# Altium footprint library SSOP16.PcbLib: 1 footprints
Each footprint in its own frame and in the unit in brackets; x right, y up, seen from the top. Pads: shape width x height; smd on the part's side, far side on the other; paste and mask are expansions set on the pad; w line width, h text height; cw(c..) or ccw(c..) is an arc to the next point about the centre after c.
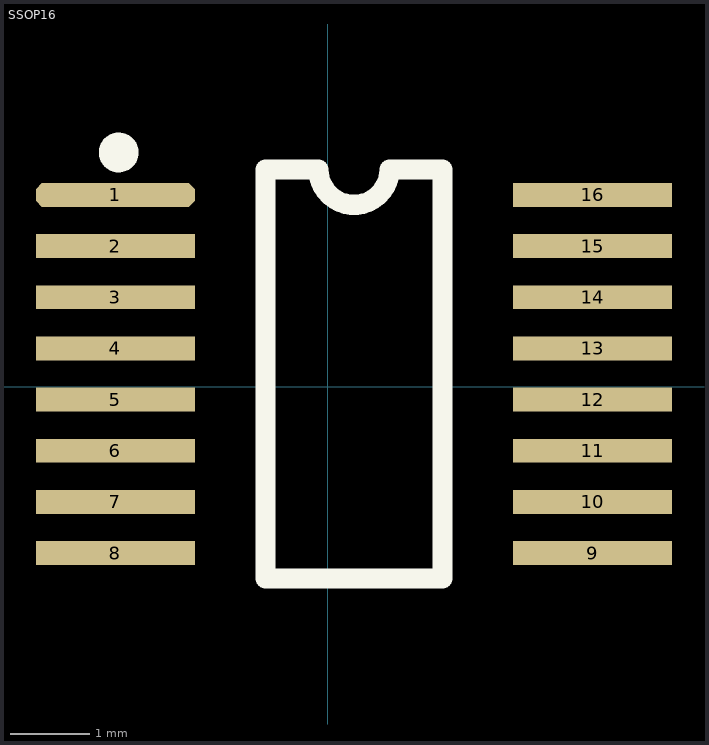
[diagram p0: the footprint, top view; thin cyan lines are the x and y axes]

## SSOP16 [mm] "SOP, 16-Leads, Body 5.0x4.0mm (max), Pitch 0.63mm, IPC Medium Density"
height 1.75
pads (16):
  oct 2x0.3 smd: 1(-2.667,2.413)
  rect 2x0.3 smd: 2(-2.667,1.77) 3(-2.667,1.127) 4(-2.667,0.484) 5(-2.667,-0.159) 6(-2.667,-0.802) 7(-2.667,-1.445) 8(-2.667,-2.088) 9(3.333,-2.088) 10(3.333,-1.445) 11(3.333,-0.802) 12(3.333,-0.159) 13(3.333,0.484) 14(3.333,1.127) 15(3.333,1.77) 16(3.333,2.413)
Top Overlay:
  circle w0.25: c-2.625,2.947 r0.125
  lines w0.254: -0.778,-2.409 1.444,-2.409 1.444,2.735 0.78,2.735 cw(c0.333,2.735) -0.114,2.735 -0.778,2.735 -0.778,-2.409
